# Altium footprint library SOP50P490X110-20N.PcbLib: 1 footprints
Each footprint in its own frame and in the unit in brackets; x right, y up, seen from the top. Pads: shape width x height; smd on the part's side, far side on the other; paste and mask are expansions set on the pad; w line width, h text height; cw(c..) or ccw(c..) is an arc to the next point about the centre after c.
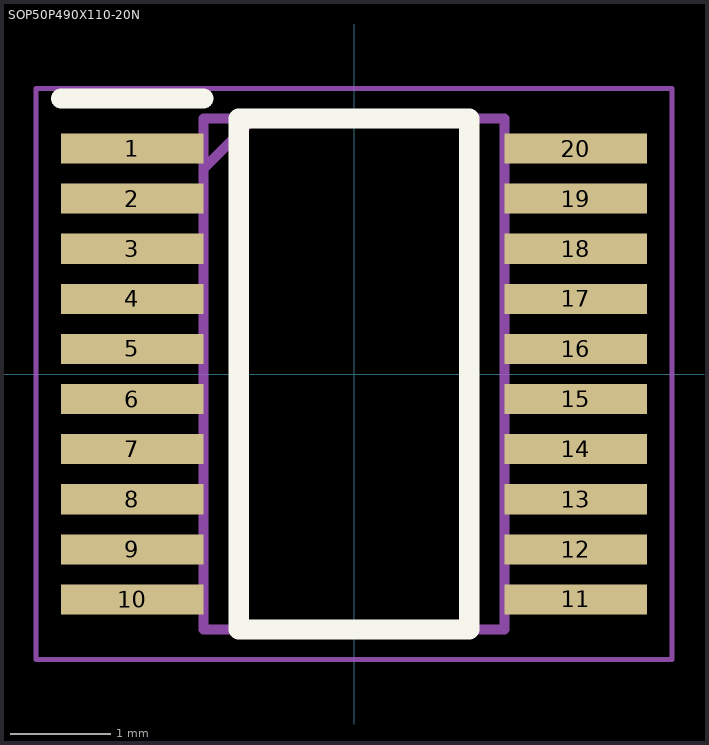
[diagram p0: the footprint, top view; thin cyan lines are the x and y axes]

## SOP50P490X110-20N [mm]
pads (20):
  rect 1.425x0.3 smd: 1(-2.212,2.25) 2(-2.212,1.75) 3(-2.212,1.25) 4(-2.212,0.75) 5(-2.212,0.25) 6(-2.212,-0.25) 7(-2.212,-0.75) 8(-2.212,-1.25) 9(-2.212,-1.75) 10(-2.212,-2.25) 11(2.212,-2.25) 12(2.212,-1.75) 13(2.212,-1.25) 14(2.212,-0.75) 15(2.212,-0.25) 16(2.212,0.25) 17(2.212,0.75) 18(2.212,1.25) 19(2.212,1.75) 20(2.212,2.25)
Top Overlay:
  lines w0.2: -2.925,2.75 -1.5,2.75 ; -1.15,-2.55 1.15,-2.55 1.15,2.55 -1.15,2.55 -1.15,-2.55
Mechanical 15:
  lines w0.1: -1.5,2.05 -1,2.55 ; -1.5,-2.55 1.5,-2.55 1.5,2.55 -1.5,2.55 -1.5,-2.55
Mechanical 20:
  lines w0.05: -3.175,-2.85 3.175,-2.85 3.175,2.85 -3.175,2.85 -3.175,-2.85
